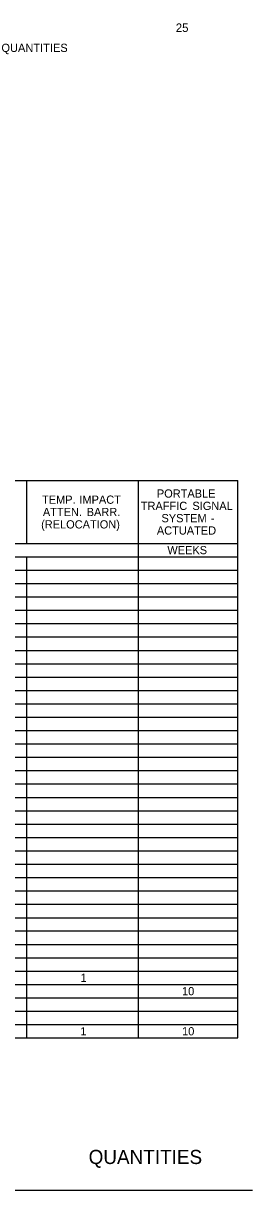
# Model space of a CAD drawing. Extents: x 1334738 to 1334853, y 402732 to 402753.
# Drawn here: x 1334765.29 to 1334769.18, y 402732.19 to 402751.98 of the extents above; entities that cross this region are included whole.
import ezdxf

# ---------------------------------------------------------------- set-up
doc = ezdxf.new("R2010")
doc.units = 0
doc.layers.add('Default', color=7, linetype='Continuous')
doc.layers.add('R_No Plot', color=7, linetype='Continuous')

msp = doc.modelspace()

# ---------------------------------------------------------------- linework, layer by layer
at = {"layer": 'Default'}
for p, q in [((1334737.688, 402744.228), (1334768.932, 402744.228)), ((1334765.351, 402743.163), (1334765.351, 402744.228)), ((1334767.244, 402734.777), (1334767.244, 402744.228)), ((1334768.932, 402734.777), (1334768.932, 402744.228)), ((1334751.401, 402743.163), (1334768.932, 402743.163)), ((1334758.348, 402743.163), (1334768.932, 402743.163)), ((1334737.688, 402742.936), (1334768.932, 402742.936)), ((1334750.279, 402742.936), (1334768.932, 402742.936)), ((1334765.351, 402734.777), (1334765.351, 402742.936)), ((1334737.688, 402742.709), (1334768.932, 402742.709)), ((1334737.688, 402742.483), (1334768.932, 402742.483)), ((1334737.688, 402742.256), (1334768.932, 402742.256)), ((1334737.688, 402742.029), (1334768.932, 402742.029)), ((1334737.688, 402741.803), (1334768.932, 402741.803)), ((1334737.688, 402741.576), (1334768.932, 402741.576)), ((1334737.688, 402741.349), (1334768.932, 402741.349)), ((1334737.688, 402741.123), (1334768.932, 402741.123)), ((1334737.688, 402740.896), (1334768.932, 402740.896)), ((1334737.688, 402740.669), (1334768.932, 402740.669)), ((1334737.688, 402740.443), (1334768.932, 402740.443)), ((1334737.688, 402740.216), (1334768.932, 402740.216)), ((1334737.688, 402739.99), (1334768.932, 402739.99)), ((1334737.688, 402739.763), (1334768.932, 402739.763)), ((1334737.688, 402739.536), (1334768.932, 402739.536)), ((1334737.688, 402739.31), (1334768.932, 402739.31)), ((1334737.688, 402739.083), (1334768.932, 402739.083)), ((1334737.688, 402738.856), (1334768.932, 402738.856)), ((1334737.688, 402738.63), (1334768.932, 402738.63)), ((1334737.688, 402738.403), (1334768.932, 402738.403)), ((1334737.688, 402738.176), (1334768.932, 402738.176)), ((1334737.688, 402737.95), (1334768.932, 402737.95)), ((1334737.688, 402737.723), (1334768.932, 402737.723)), ((1334737.688, 402737.496), (1334768.932, 402737.496)), ((1334737.688, 402737.27), (1334768.932, 402737.27)), ((1334737.688, 402737.043), (1334768.932, 402737.043)), ((1334737.688, 402736.816), (1334768.932, 402736.816)), ((1334737.688, 402736.59), (1334768.932, 402736.59)), ((1334758.348, 402736.59), (1334768.932, 402736.59)), ((1334737.688, 402736.363), (1334768.932, 402736.363)), ((1334758.348, 402736.363), (1334768.932, 402736.363)), ((1334737.688, 402736.136), (1334768.932, 402736.136)), ((1334751.401, 402736.136), (1334768.932, 402736.136)), ((1334737.688, 402735.91), (1334768.932, 402735.91)), ((1334751.401, 402735.91), (1334768.932, 402735.91)), ((1334737.688, 402735.683), (1334768.932, 402735.683)), ((1334751.401, 402735.683), (1334768.932, 402735.683)), ((1334737.688, 402735.456), (1334768.932, 402735.456)), ((1334751.401, 402735.456), (1334767.244, 402735.456)), ((1334767.244, 402735.456), (1334768.932, 402735.456)), ((1334737.688, 402735.23), (1334768.932, 402735.23)), ((1334746.131, 402735.23), (1334768.932, 402735.23)), ((1334737.688, 402735.003), (1334768.932, 402735.003)), ((1334756.013, 402735.003), (1334768.932, 402735.003)), ((1334737.688, 402734.777), (1334768.932, 402734.777))]:
    msp.add_line(p, q, dxfattribs=at)
at = {"layer": 'R_No Plot'}
msp.add_line((1334769.182, 402732.187), (1334737.564, 402732.187), dxfattribs=at)

# ---------------------------------------------------------------- texts
at = {"layer": 'Default'}
for s, height, p in [('PORTABLE', 0.1395, (1334767.557, 402743.939)), ('TEMP.', 0.1395, (1334765.608, 402743.835)), (' IMPACT', 0.1395, (1334766.19, 402743.835)), ('TRAFFIC', 0.1395, (1334767.284, 402743.73)), (' SIGNAL', 0.1395, (1334768.108, 402743.73)), ('ATTEN.', 0.1395, (1334765.623, 402743.626)), (' BARR.', 0.1395, (1334766.314, 402743.626)), ('SYSTEM', 0.1395, (1334767.635, 402743.521)), ('(RELOCATION)', 0.13948, (1334765.593, 402743.416)), ('ACTUATED', 0.1395, (1334767.557, 402743.312)), (' -', 0.1395, (1334768.423, 402743.521)), ('WEEKS', 0.1395, (1334767.735, 402742.98)), ('1', 0.139, (1334766.261, 402735.727)), ('10', 0.1395, (1334767.984, 402735.5)), ('1', 0.139, (1334766.259, 402734.82)), ('10', 0.1395, (1334767.985, 402734.82))]:
    msp.add_text(s, height=height, dxfattribs=at).set_placement(p)
at = {"layer": 'R_No Plot'}
for s, height, p in [('25', 0.1444, (1334767.878, 402751.836)), ('QUANTITIES', 0.24, (1334766.399, 402732.638))]:
    msp.add_text(s, height=height, dxfattribs=at).set_placement(p)
msp.add_text('QUANTITIES', height=0.14, rotation=360, dxfattribs=at).set_placement((1334764.92, 402751.497))

doc.saveas('drawing.dxf')
